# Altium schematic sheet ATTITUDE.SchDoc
size A4
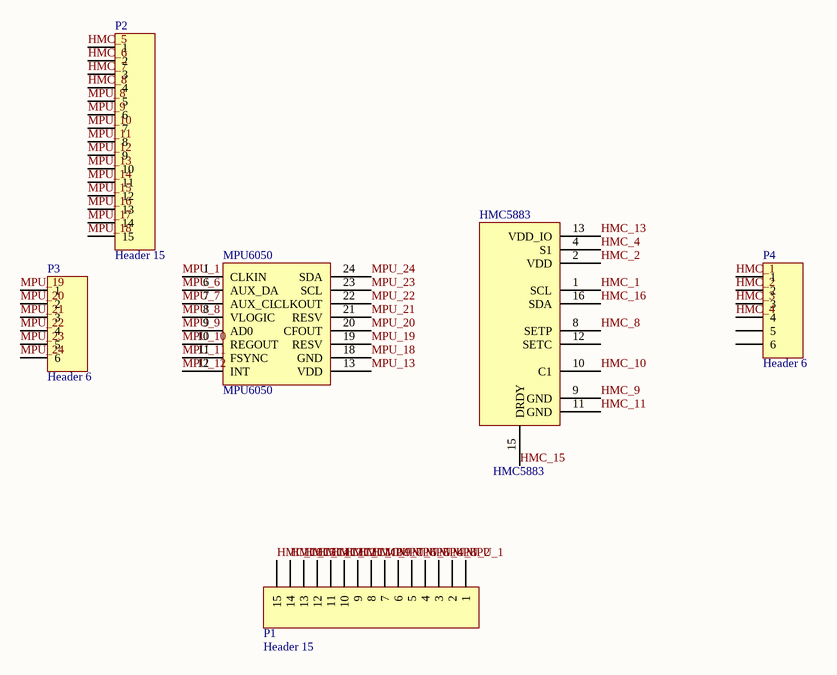
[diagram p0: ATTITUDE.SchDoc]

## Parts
HMC5883  HMC5883  [HMC5883]
MPU6050  MPU6050  [MPU6050]
P1  Header 15  [HDR1X15]
P2  Header 15  [HDR1X15]
P3  Header 6  [HDR1X6]
P4  Header 6  [HDR1X6]

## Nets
HMC_1: HMC5883.1(SCL) P4.1
HMC_2: HMC5883.2(VDD) P4.2
HMC_3: P4.3
HMC_4: HMC5883.4(S1) P4.4
HMC_5: P2.1
HMC_6: P2.2
HMC_7: P2.3
HMC_8: HMC5883.8(SETP) P2.4
HMC_9: HMC5883.9(GND) P1.8
HMC_10: HMC5883.10(C1) P1.9
HMC_11: HMC5883.11(GND) P1.10
HMC_12: P1.11
HMC_13: HMC5883.13(VDD_IO) P1.12
HMC_14: P1.13
HMC_15: HMC5883.15(DRDY) P1.14
HMC_16: HMC5883.16(SDA) P1.15
MPU_1: MPU6050.1(CLKIN) P1.1
MPU_2: P1.2
MPU_3: P1.3
MPU_4: P1.4
MPU_5: P1.5
MPU_6: MPU6050.6(AUX_DA) P1.6
MPU_7: MPU6050.7(AUX_CL) P1.7
MPU_8: MPU6050.8(VLOGIC) P2.5
MPU_9: MPU6050.9(AD0) P2.6
MPU_10: MPU6050.10(REGOUT) P2.7
MPU_11: MPU6050.11(FSYNC) P2.8
MPU_12: MPU6050.12(INT) P2.9
MPU_13: MPU6050.13(VDD) P2.10
MPU_14: P2.11
MPU_15: P2.12
MPU_16: P2.13
MPU_17: P2.14
MPU_18: MPU6050.18(GND) P2.15
MPU_19: MPU6050.19(RESV) P3.1
MPU_20: MPU6050.20(CFOUT) P3.2
MPU_21: MPU6050.21(RESV) P3.3
MPU_22: MPU6050.22(CLKOUT) P3.4
MPU_23: MPU6050.23(SCL) P3.5
MPU_24: MPU6050.24(SDA) P3.6

Not connected (* = marked no-connect by the designer): HMC5883 12(SETC); P4 5 6

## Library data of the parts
HMC5883 MPU6050 = Component_1
P1 P2 = Header 15: Header, 15-Pin
P3 P4 = Header 6: Header, 6-Pin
